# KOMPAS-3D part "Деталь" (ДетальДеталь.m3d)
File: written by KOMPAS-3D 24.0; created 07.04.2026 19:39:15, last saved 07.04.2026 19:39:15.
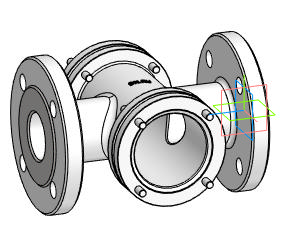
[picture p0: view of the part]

Document properties: Автор: Main; Полное имя файла: D:\DN.ru Аутсерс\Стекло смотровое DN.ru\Исходники\Стекло смотровое DN.ru SG2-34G-F тип В ГОСТ 21836-2021 Ду50 Ру40, углеродистая сталь, фланцевое\ДетальДеталь.m3d

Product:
- Body: Твердое тело1  | qty 1
- Part/product: Деталь
    additional columns: Типовые

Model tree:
1. Твердое тело1  (labels: Твердое тело1)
